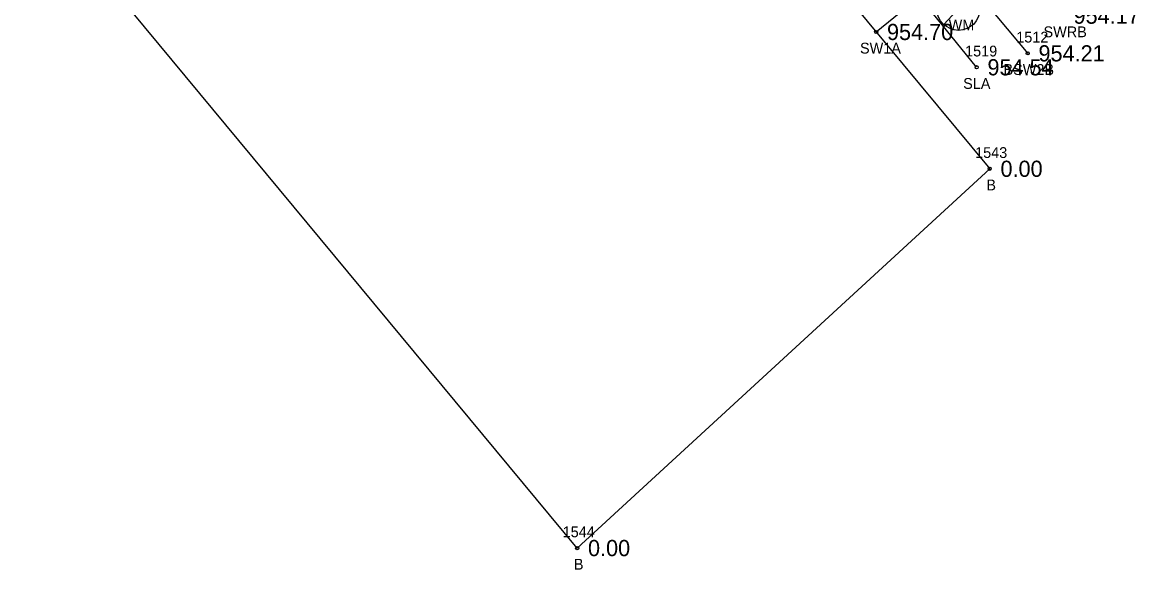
# Model space of a CAD drawing. Extents: x 1575382 to 1578175, y 1099175 to 1101955.
# Drawn here: x 1576458 to 1576561.5, y 1099349.9 to 1099400.6 of the extents above; entities that cross this region are included whole.
import ezdxf

# ---------------------------------------------------------------- set-up
doc = ezdxf.new("R2010")
doc.units = 0
for name, color, linetype in [('RD_EX_Bldg', 7, 'Continuous'), ('RD_EX_Bldg_txCode', 7, 'Continuous'), ('RD_EX_Conc', 7, 'Continuous'), ('RD_EX_Conc_txCode', 7, 'Continuous'), ('RD_EX_TX_Bldg_ELEV', 7, 'Continuous'), ('RD_EX_TX_Conc_ELEV', 7, 'Continuous'), ('RD_EX_TX_VEG_ELEV', 7, 'Continuous'), ('RD_EX_UT', 7, 'Continuous'), ('RD_EX_UT_txCode', 7, 'Continuous'), ('RD_EX_VEG', 7, 'Continuous'), ('RD_EX_VEG_txCode', 7, 'Continuous'), ('RD_SMD_Locator', 7, 'Continuous')]:
    doc.layers.add(name, color=color, linetype=linetype)

msp = doc.modelspace()

# ---------------------------------------------------------------- linework, layer by layer
at = {"layer": 'RD_EX_Bldg'}
msp.add_lwpolyline([(1576481.32, 1099466.88), (1576547.69, 1099387), (1576509.46, 1099351.88), (1576443.09, 1099431.76), (1576481.32, 1099466.88)], dxfattribs=at)
at = {"layer": 'RD_EX_Conc'}
msp.add_line((1576537.17, 1099399.67), (1576544.52, 1099405.7), dxfattribs=at)
msp.add_lwpolyline([(1576417.79, 1099558.83), (1576419.81, 1099556.41), (1576422.78, 1099552.79), (1576443.67, 1099527.67), (1576447.39, 1099523.04), (1576450.38, 1099519.36), (1576454.58, 1099514.36), (1576470.78, 1099494.84), (1576474, 1099490.99), (1576488.02, 1099473.93), (1576497.44, 1099462.54), (1576500.63, 1099458.76), (1576516.67, 1099439.27), (1576520.69, 1099434.46), (1576523.68, 1099430.77), (1576527.93, 1099425.88), (1576541.66, 1099409.22), (1576544.52, 1099405.7), (1576551.21, 1099397.69)], dxfattribs=at)
at = {"layer": 'RD_EX_UT'}
msp.add_line((1576543.44, 1099400.36), (1576546.11, 1099403.25), dxfattribs=at)
msp.add_circle((1576544.79, 1099401.82), 2, dxfattribs=at)
at = {"layer": 'RD_EX_VEG'}
msp.add_line((1576546.48, 1099396.4), (1576541.43, 1099402.63), dxfattribs=at)
at = {"layer": 'RD_SMD_Locator'}
for centre in [(1576537.17, 1099399.67), (1576551.21, 1099397.69), (1576546.48, 1099396.4), (1576547.69, 1099387), (1576509.46, 1099351.88)]:
    msp.add_circle(centre, 0.15, dxfattribs=at)

# ---------------------------------------------------------------- texts
at = {"layer": 'RD_EX_Bldg_txCode'}
for s, p in [('1543', (1576546.34, 1099388)), ('B', (1576547.38, 1099385)), ('1544', (1576508.11, 1099352.88)), ('B', (1576509.15, 1099349.88))]:
    msp.add_text(s, height=1, dxfattribs=at).set_placement(p)
at = {"layer": 'RD_EX_Conc_txCode'}
for s, p in [('1512', (1576550.15, 1099398.69)), ('SWRB', (1576552.68, 1099399.18)), ('SW1A', (1576535.67, 1099397.67)), ('BSW2B', (1576548.97, 1099395.69))]:
    msp.add_text(s, height=1, dxfattribs=at).set_placement(p)
at = {"layer": 'RD_EX_TX_Bldg_ELEV'}
for p in [(1576548.69, 1099386.25), (1576510.46, 1099351.13)]:
    msp.add_text('0.00', height=1.5, dxfattribs=at).set_placement(p)
at = {"layer": 'RD_EX_TX_Conc_ELEV'}
for s, p in [('954.17', (1576555.46, 1099400.43)), ('954.70', (1576538.17, 1099398.92)), ('954.21', (1576552.21, 1099396.94))]:
    msp.add_text(s, height=1.5, dxfattribs=at).set_placement(p)
at = {"layer": 'RD_EX_TX_VEG_ELEV'}
msp.add_text('954.54', height=1.5, dxfattribs=at).set_placement((1576547.48, 1099395.65))
at = {"layer": 'RD_EX_UT_txCode'}
msp.add_text('WM', height=1, dxfattribs=at).set_placement((1576543.89, 1099399.82))
at = {"layer": 'RD_EX_VEG_txCode'}
for s, p in [('1519', (1576545.41, 1099397.4)), ('SLA', (1576545.23, 1099394.4))]:
    msp.add_text(s, height=1, dxfattribs=at).set_placement(p)

doc.saveas('drawing.dxf')
